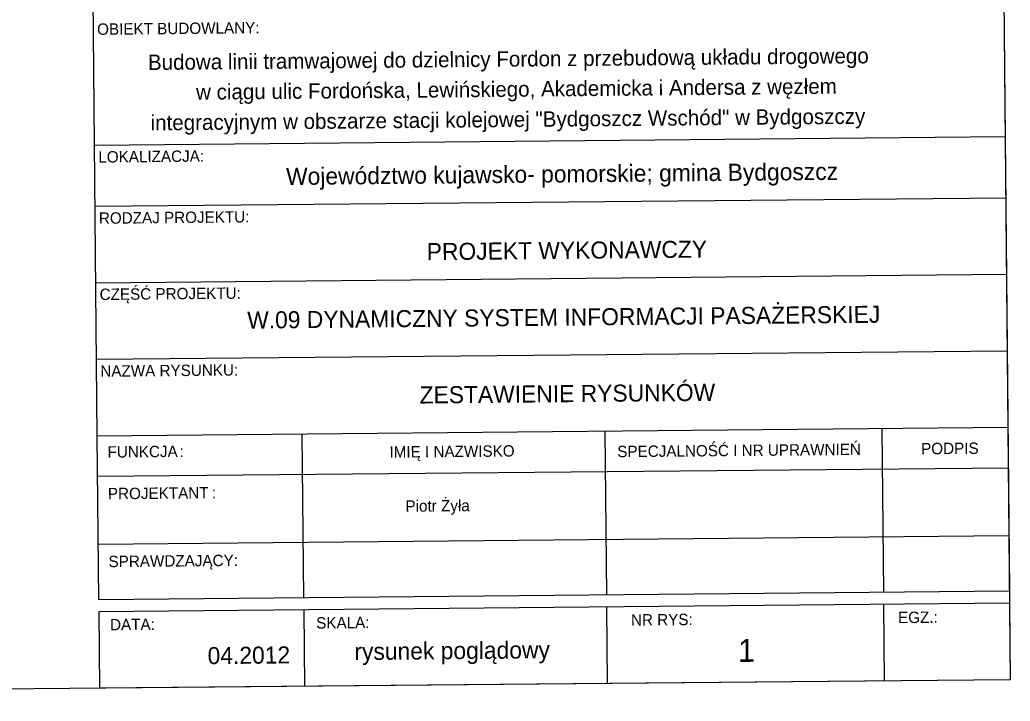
# Model space of a CAD drawing. Extents: x 6503541 to 6503743, y 5888004 to 5888145.
# Drawn here: x 6503655.8 to 6503742.8, y 5888004.1 to 5888064 of the extents above; entities that cross this region are included whole.
import ezdxf

# ---------------------------------------------------------------- set-up
doc = ezdxf.new("R2010")
doc.units = 0
for name, color, linetype in [('SA_Linie-020', 7, 'Continuous'), ('SA_Stempel_Text-020', 7, 'Continuous'), ('SA_Stempel_Text-030', 7, 'Continuous'), ('SA_Stempel_Text-035', 7, 'Continuous'), ('SA_Unterschrift_Text', 7, 'Continuous'), ('tabela', 7, 'Continuous')]:
    doc.layers.add(name, color=color, linetype=linetype)

msp = doc.modelspace()

# ---------------------------------------------------------------- linework, layer by layer
at = {"layer": 'SA_Linie-020'}
for p, q in [((6503742.16, 5888074.571), (6503742.728, 5888013.78)), ((6503662.597, 5888027.406), (6503662.163, 5888073.824)), ((6503742.355, 5888053.688), (6503662.358, 5888052.941)), ((6503742.405, 5888048.312), (6503662.409, 5888047.565)), ((6503742.468, 5888041.592), (6503662.471, 5888040.845)), ((6503742.468, 5888041.592), (6503662.471, 5888040.845)), ((6503742.531, 5888034.873), (6503662.534, 5888034.126)), ((6503742.593, 5888028.153), (6503662.597, 5888027.406)), ((6503680.752, 5888013.202), (6503680.618, 5888027.575)), ((6503707.193, 5888027.828), (6503707.327, 5888013.45)), ((6503731.528, 5888028.05), (6503731.662, 5888013.677)), ((6503662.731, 5888013.033), (6503662.597, 5888027.406)), ((6503742.627, 5888024.594), (6503662.63, 5888023.847)), ((6503742.682, 5888018.635), (6503662.686, 5888017.888)), ((6503742.728, 5888013.78), (6503662.731, 5888013.033)), ((6503742.738, 5888012.72), (6503662.741, 5888011.973)), ((6503742.738, 5888012.72), (6503742.8, 5888006.001)), ((6503662.741, 5888011.973), (6503662.804, 5888005.254)), ((6503680.762, 5888012.142), (6503680.824, 5888005.422)), ((6503707.337, 5888012.39), (6503707.4, 5888005.67)), ((6503731.672, 5888012.617), (6503731.735, 5888005.897)), ((6503742.8, 5888006.001), (6503662.804, 5888005.254))]:
    msp.add_line(p, q, dxfattribs=at)
at = {"layer": 'tabela'}
for p, q in [((6503741.498, 5888145.448), (6503742.8, 5888006.001)), ((6503742.8, 5888006.001), (6503541.816, 5888004.124))]:
    msp.add_line(p, q, dxfattribs=at)

# ---------------------------------------------------------------- texts
at = {"layer": 'SA_Stempel_Text-020'}
for s, p in [('OBIEKT BUDOWLANY:', (6503662.598, 5888062.652)), ('LOKALIZACJA:', (6503662.703, 5888051.428)), ('RODZAJ PROJEKTU:', (6503662.753, 5888046.052)), ('CZĘŚĆ PROJEKTU:', (6503662.816, 5888039.359)), ('NAZWA RYSUNKU:', (6503662.879, 5888032.613)), ('IMIĘ I NAZWISKO', (6503688.277, 5888025.512)), ('SPECJALNOŚĆ I NR UPRAWNIEŃ', (6503708.29, 5888025.553)), ('PODPIS', (6503734.981, 5888025.802)), ('FUNKCJA', (6503663.511, 5888025.515)), (':', (6503669.84, 5888025.574)), ('PROJEKTANT', (6503663.545, 5888021.855)), (':', (6503672.677, 5888021.94)), ('SPRAWDZAJĄCY:', (6503663.6, 5888015.896)), ('EGZ.:', (6503732.954, 5888010.976)), ('DATA:', (6503663.732, 5888010.347)), ('SKALA:', (6503681.84, 5888010.499)), ('NR RYS:', (6503709.493, 5888010.757))]:
    msp.add_text(s, height=1, rotation=0.53502, dxfattribs=at).set_placement(p)
at = {"layer": 'SA_Stempel_Text-030'}
for s, height, p in [('rysunek poglądowy', 1.5, (6503685.2, 5888007.736)), ('1', 2, (6503718.902, 5888007.571)), ('04.2012', 1.5, (6503672.304, 5888007.376))]:
    msp.add_text(s, height=height, rotation=0.53502, dxfattribs=at).set_placement(p)
at = {"layer": 'SA_Stempel_Text-035'}
for s, height, p in [('Budowa linii tramwajowej do dzielnicy Fordon z przebudową układu drogowego', 1.35, (6503667.063, 5888059.562)), ('w ciągu ulic Fordońska, Lewińskiego, Akademicka i Andersa z węzłem', 1.35, (6503671.289, 5888056.954)), ('integracyjnym w obszarze stacji kolejowej "Bydgoszcz Wschód" w Bydgoszczy', 1.35, (6503667.294, 5888054.256)), ('Województwo kujawsko- pomorskie; gmina Bydgoszcz', 1.5, (6503679.196, 5888049.464)), ('PROJEKT WYKONAWCZY', 1.5, (6503691.552, 5888042.859)), ('W.09 DYNAMICZNY SYSTEM INFORMACJI PASAŻERSKIEJ', 1.5, (6503675.781, 5888036.846)), ('ZESTAWIENIE RYSUNKÓW', 1.5, (6503690.926, 5888030.267))]:
    msp.add_text(s, height=height, rotation=0.53502, dxfattribs=at).set_placement(p)
at = {"layer": 'SA_Unterschrift_Text'}
msp.add_text('Piotr Żyła', height=1, rotation=0.53502, dxfattribs=at).set_placement((6503689.684, 5888020.761))

doc.saveas('drawing.dxf')
